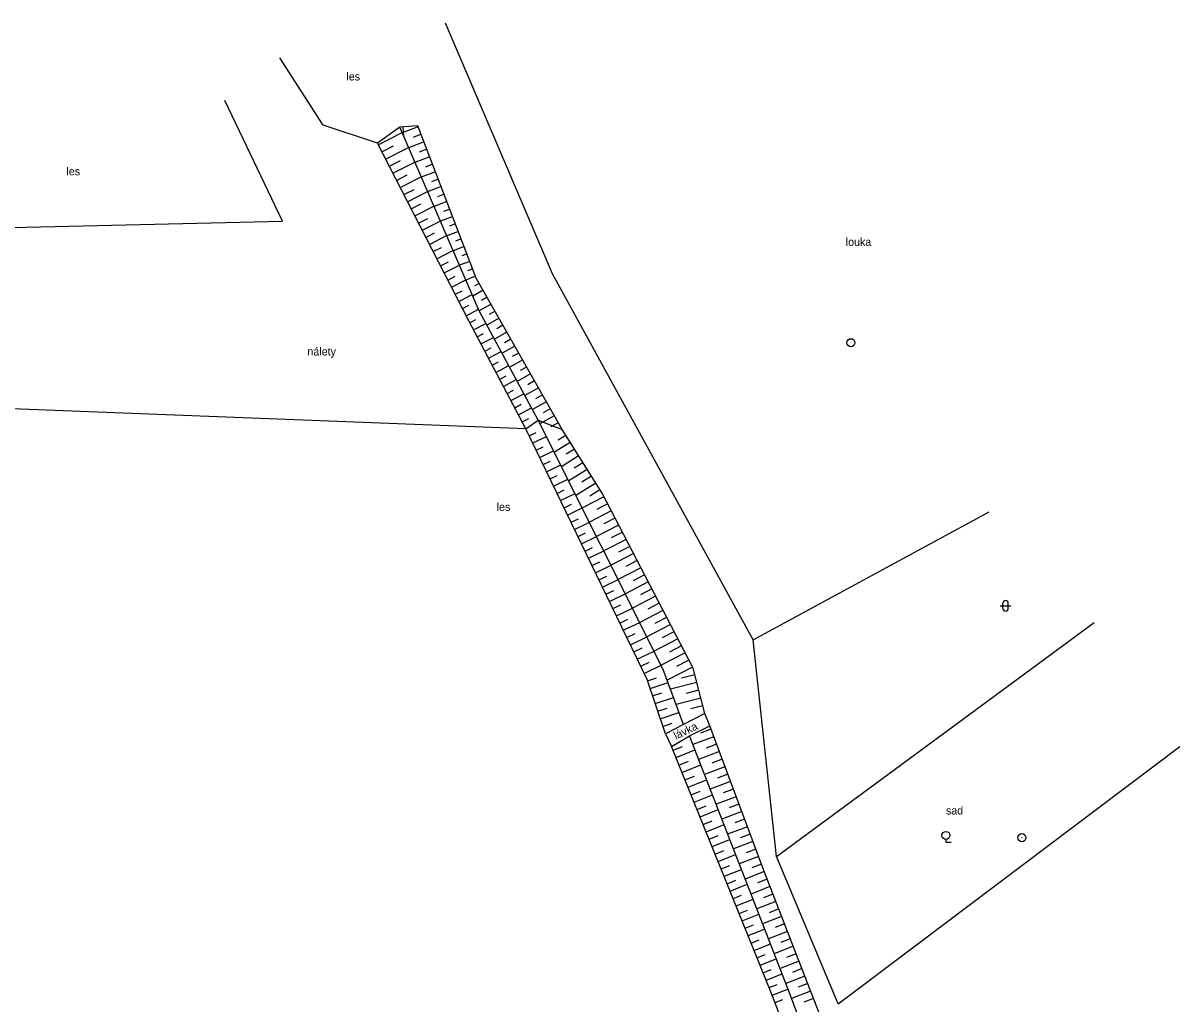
# Model space of a CAD drawing. Extents: x -762483 to -761175, y -1154655 to -1152452.
# Drawn here: x -761757.5 to -761649, y -1152873.6 to -1152781.8 of the extents above; entities that cross this region are included whole.
import ezdxf

# ---------------------------------------------------------------- set-up
doc = ezdxf.new("R2010")
doc.units = 0
for name, color, linetype in [('MAP_ZN_BP', 7, 'Continuous'), ('POMOC_POPIS', 7, 'Continuous'), ('VÝŠKOPIS', 7, 'Continuous'), ('ZELEŇ', 7, 'Continuous'), ('ZN_DOPLŇKOVÉ', 7, 'Continuous'), ('ZN_KULTUR', 7, 'Continuous')]:
    doc.layers.add(name, color=color, linetype=linetype)

msp = doc.modelspace()

# ---------------------------------------------------------------- linework, layer by layer
at = {"layer": 'MAP_ZN_BP'}
for centre, radius in [((-761679.87, -1152811.69), 0.375), ((-761679.87, -1152811.69), 0.0005), ((-761663.84, -1152858.07), 0.375), ((-761663.84, -1152858.07), 0.0005)]:
    msp.add_circle(centre, radius, dxfattribs=at)
at = {"layer": 'VÝŠKOPIS'}
for p, q in [((-761720.43, -1152791.46), (-761721.93, -1152792.04)), ((-761721.87, -1152791.48), (-761721.81, -1152792.34)), ((-761724.18, -1152793.16), (-761721.95, -1152792.01)), ((-761720.16, -1152792.16), (-761720.9, -1152792.45)), ((-761723.84, -1152793.82), (-761722.75, -1152793.26)), ((-761723.5, -1152794.49), (-761721.35, -1152793.39)), ((-761719.89, -1152792.86), (-761721.34, -1152793.42)), ((-761719.62, -1152793.57), (-761720.33, -1152793.84)), ((-761723.16, -1152795.16), (-761722.11, -1152794.62)), ((-761722.81, -1152795.82), (-761720.76, -1152794.77)), ((-761719.35, -1152794.27), (-761720.74, -1152794.8)), ((-761718.81, -1152795.67), (-761720.15, -1152796.18)), ((-761719.08, -1152794.97), (-761719.76, -1152795.23)), ((-761722.47, -1152796.49), (-761721.46, -1152795.97)), ((-761722.13, -1152797.16), (-761720.16, -1152796.15)), ((-761718.55, -1152796.37), (-761719.2, -1152796.62)), ((-761721.78, -1152797.82), (-761720.82, -1152797.33)), ((-761721.44, -1152798.49), (-761719.56, -1152797.53)), ((-761718.28, -1152797.07), (-761719.55, -1152797.55)), ((-761718.01, -1152797.77), (-761718.63, -1152798.01)), ((-761721.1, -1152799.16), (-761720.18, -1152798.69)), ((-761720.75, -1152799.82), (-761718.97, -1152798.91)), ((-761717.74, -1152798.47), (-761718.95, -1152798.93)), ((-761717.47, -1152799.17), (-761718.06, -1152799.39)), ((-761720.41, -1152800.49), (-761719.54, -1152800.04)), ((-761717.2, -1152799.87), (-761718.36, -1152800.31)), ((-761720.07, -1152801.16), (-761718.37, -1152800.29)), ((-761716.66, -1152801.27), (-761717.76, -1152801.69)), ((-761716.93, -1152800.57), (-761717.5, -1152800.78)), ((-761719.72, -1152801.83), (-761718.9, -1152801.4)), ((-761719.38, -1152802.49), (-761717.77, -1152801.66)), ((-761716.4, -1152801.97), (-761716.93, -1152802.17)), ((-761719.04, -1152803.16), (-761718.25, -1152802.76)), ((-761718.69, -1152803.83), (-761717.18, -1152803.04)), ((-761716.13, -1152802.67), (-761717.17, -1152803.07)), ((-761715.86, -1152803.37), (-761716.36, -1152803.56)), ((-761718.35, -1152804.49), (-761717.61, -1152804.11)), ((-761718.01, -1152805.16), (-761716.58, -1152804.42)), ((-761715.59, -1152804.07), (-761716.57, -1152804.44)), ((-761717.66, -1152805.83), (-761716.97, -1152805.47)), ((-761715.05, -1152805.47), (-761715.97, -1152805.82)), ((-761715.32, -1152804.77), (-761715.8, -1152804.95)), ((-761717.32, -1152806.49), (-761715.98, -1152805.8)), ((-761714.71, -1152806.13), (-761715.16, -1152806.39)), ((-761716.98, -1152807.16), (-761716.33, -1152806.83)), ((-761716.63, -1152807.83), (-761715.38, -1152807.18)), ((-761714.34, -1152806.78), (-761715.32, -1152807.34)), ((-761713.97, -1152807.44), (-761714.49, -1152807.73)), ((-761716.29, -1152808.49), (-761715.69, -1152808.18)), ((-761715.95, -1152809.16), (-761714.79, -1152808.56)), ((-761713.6, -1152808.09), (-761714.72, -1152808.72)), ((-761713.23, -1152808.74), (-761713.79, -1152809.06)), ((-761715.6, -1152809.83), (-761715.03, -1152809.52)), ((-761715.25, -1152810.49), (-761714.09, -1152809.88)), ((-761712.86, -1152809.4), (-761714, -1152810.04)), ((-761714.9, -1152811.15), (-761714.32, -1152810.84)), ((-761712.12, -1152810.7), (-761713.29, -1152811.36)), ((-761712.49, -1152810.05), (-761713.07, -1152810.38)), ((-761714.55, -1152811.81), (-761713.38, -1152811.2)), ((-761714.2, -1152812.48), (-761713.61, -1152812.17)), ((-761711.38, -1152812.01), (-761712.58, -1152812.68)), ((-761711.75, -1152811.35), (-761712.34, -1152811.69)), ((-761713.85, -1152813.14), (-761712.67, -1152812.52)), ((-761711.01, -1152812.66), (-761711.62, -1152813)), ((-761713.5, -1152813.8), (-761712.9, -1152813.49)), ((-761713.15, -1152814.47), (-761711.95, -1152813.84)), ((-761710.64, -1152813.31), (-761711.86, -1152814)), ((-761710.27, -1152813.97), (-761710.89, -1152814.31)), ((-761712.8, -1152815.13), (-761712.2, -1152814.81)), ((-761712.44, -1152815.79), (-761711.24, -1152815.15)), ((-761709.9, -1152814.62), (-761711.15, -1152815.32)), ((-761709.54, -1152815.27), (-761710.16, -1152815.63)), ((-761712.09, -1152816.46), (-761711.49, -1152816.13)), ((-761711.74, -1152817.12), (-761710.53, -1152816.47)), ((-761709.17, -1152815.92), (-761710.43, -1152816.64)), ((-761711.39, -1152817.78), (-761710.78, -1152817.46)), ((-761708.43, -1152817.23), (-761709.72, -1152817.96)), ((-761708.8, -1152816.58), (-761709.44, -1152816.94)), ((-761711.04, -1152818.44), (-761709.81, -1152817.79)), ((-761707.69, -1152818.53), (-761709.02, -1152819.29)), ((-761708.06, -1152817.88), (-761708.71, -1152818.25)), ((-761710.69, -1152819.11), (-761710.07, -1152818.78)), ((-761707.32, -1152819.19), (-761708, -1152819.57)), ((-761710.03, -1152820.41), (-761709.39, -1152820.1)), ((-761709.7, -1152821.09), (-761708.42, -1152820.47)), ((-761706.6, -1152820.4), (-761707.31, -1152820.84)), ((-761709.38, -1152821.76), (-761708.73, -1152821.45)), ((-761709.05, -1152822.44), (-761707.75, -1152821.81)), ((-761706.2, -1152821.03), (-761707.67, -1152821.96)), ((-761705.8, -1152821.67), (-761706.57, -1152822.15)), ((-761708.72, -1152823.11), (-761708.07, -1152822.8)), ((-761705.4, -1152822.3), (-761707, -1152823.31)), ((-761705, -1152822.94), (-761705.83, -1152823.46)), ((-761708.4, -1152823.79), (-761707.08, -1152823.15)), ((-761704.6, -1152823.57), (-761706.32, -1152824.65)), ((-761708.07, -1152824.46), (-761707.4, -1152824.14)), ((-761707.74, -1152825.14), (-761706.4, -1152824.49)), ((-761703.8, -1152824.84), (-761705.65, -1152826)), ((-761704.2, -1152824.21), (-761705.09, -1152824.77)), ((-761707.42, -1152825.81), (-761706.74, -1152825.49)), ((-761707.09, -1152826.49), (-761705.73, -1152825.83)), ((-761703.03, -1152826.12), (-761705.05, -1152827.18)), ((-761703.4, -1152825.48), (-761704.36, -1152826.07)), ((-761706.76, -1152827.16), (-761706.08, -1152826.83)), ((-761706.43, -1152827.84), (-761705.06, -1152827.17)), ((-761702.69, -1152826.79), (-761703.7, -1152827.32)), ((-761706.11, -1152828.51), (-761705.41, -1152828.18)), ((-761702.34, -1152827.46), (-761704.38, -1152828.52)), ((-761701.99, -1152828.12), (-761703.02, -1152828.65)), ((-761705.78, -1152829.19), (-761704.38, -1152828.51)), ((-761705.45, -1152829.86), (-761704.75, -1152829.52)), ((-761701.65, -1152828.79), (-761703.71, -1152829.86)), ((-761701.3, -1152829.45), (-761702.34, -1152829.99)), ((-761705.13, -1152830.54), (-761703.71, -1152829.85)), ((-761700.95, -1152830.12), (-761703.03, -1152831.2)), ((-761704.8, -1152831.21), (-761704.09, -1152830.87)), ((-761704.47, -1152831.89), (-761703.04, -1152831.19)), ((-761700.26, -1152831.45), (-761702.36, -1152832.54)), ((-761700.61, -1152830.78), (-761701.65, -1152831.33)), ((-761704.15, -1152832.56), (-761703.42, -1152832.21)), ((-761703.82, -1152833.24), (-761702.36, -1152832.53)), ((-761699.57, -1152832.78), (-761701.69, -1152833.88)), ((-761699.92, -1152832.11), (-761700.97, -1152832.66)), ((-761703.49, -1152833.91), (-761702.76, -1152833.56)), ((-761703.17, -1152834.59), (-761701.69, -1152833.87)), ((-761699.22, -1152833.44), (-761700.29, -1152834)), ((-761702.84, -1152835.26), (-761702.1, -1152834.9)), ((-761698.88, -1152834.11), (-761701.01, -1152835.22)), ((-761698.53, -1152834.77), (-761699.61, -1152835.33)), ((-761702.51, -1152835.94), (-761701.02, -1152835.21)), ((-761698.19, -1152835.44), (-761700.34, -1152836.56)), ((-761702.19, -1152836.61), (-761701.43, -1152836.25)), ((-761701.86, -1152837.29), (-761700.34, -1152836.56)), ((-761697.49, -1152836.77), (-761699.67, -1152837.9)), ((-761697.84, -1152836.11), (-761698.92, -1152836.67)), ((-761701.53, -1152837.96), (-761700.77, -1152837.59)), ((-761701.21, -1152838.64), (-761699.67, -1152837.9)), ((-761696.8, -1152838.1), (-761699, -1152839.24)), ((-761697.15, -1152837.44), (-761698.24, -1152838)), ((-761700.88, -1152839.31), (-761700.11, -1152838.94)), ((-761700.55, -1152839.99), (-761699, -1152839.24)), ((-761696.46, -1152838.77), (-761697.56, -1152839.34)), ((-761700.23, -1152840.66), (-761699.44, -1152840.29)), ((-761696.11, -1152839.43), (-761698.32, -1152840.58)), ((-761695.76, -1152840.1), (-761696.87, -1152840.68)), ((-761699.9, -1152841.34), (-761698.32, -1152840.58)), ((-761695.42, -1152840.76), (-761697.65, -1152841.92)), ((-761695.07, -1152841.43), (-761696.21, -1152842.02)), ((-761699.57, -1152842.01), (-761698.78, -1152841.63)), ((-761699.25, -1152842.69), (-761697.65, -1152841.92)), ((-761694.73, -1152842.09), (-761697.09, -1152843.32)), ((-761698.93, -1152843.37), (-761698.1, -1152843.09)), ((-761698.7, -1152844.08), (-761697.01, -1152843.52)), ((-761694.32, -1152843.54), (-761696.78, -1152844.17)), ((-761694.51, -1152842.81), (-761695.77, -1152843.14)), ((-761698.46, -1152844.79), (-761697.61, -1152844.51)), ((-761694.14, -1152844.26), (-761695.33, -1152844.57)), ((-761698.22, -1152845.5), (-761696.5, -1152844.93)), ((-761693.95, -1152844.99), (-761696.26, -1152845.59)), ((-761693.76, -1152845.71), (-761694.88, -1152846.01)), ((-761697.98, -1152846.22), (-761697.11, -1152845.93)), ((-761697.75, -1152846.93), (-761695.99, -1152846.34)), ((-761697.51, -1152847.64), (-761696.62, -1152847.34)), ((-761692.99, -1152847.9), (-761693.97, -1152848.27)), ((-761692.72, -1152848.61), (-761694.69, -1152849.34)), ((-761696.55, -1152849.88), (-761695.66, -1152849.52)), ((-761696.27, -1152850.57), (-761694.49, -1152849.85)), ((-761692.2, -1152850.01), (-761694.15, -1152850.74)), ((-761692.46, -1152849.31), (-761693.44, -1152849.67)), ((-761695.99, -1152851.27), (-761695.1, -1152850.91)), ((-761691.94, -1152850.71), (-761692.91, -1152851.08)), ((-761695.71, -1152851.96), (-761693.95, -1152851.25)), ((-761695.43, -1152852.66), (-761694.55, -1152852.3)), ((-761691.68, -1152851.42), (-761693.6, -1152852.14)), ((-761691.41, -1152852.12), (-761692.37, -1152852.48)), ((-761695.14, -1152853.35), (-761693.4, -1152852.65)), ((-761691.15, -1152852.82), (-761693.06, -1152853.53)), ((-761694.86, -1152854.05), (-761694, -1152853.7)), ((-761694.58, -1152854.74), (-761692.86, -1152854.05)), ((-761690.63, -1152854.23), (-761692.51, -1152854.93)), ((-761690.89, -1152853.53), (-761691.84, -1152853.88)), ((-761694.3, -1152855.44), (-761693.44, -1152855.09)), ((-761694.02, -1152856.13), (-761692.32, -1152855.44)), ((-761690.37, -1152854.93), (-761691.3, -1152855.28)), ((-761693.73, -1152856.83), (-761692.89, -1152856.49)), ((-761690.1, -1152855.63), (-761691.97, -1152856.33)), ((-761689.84, -1152856.34), (-761690.77, -1152856.68)), ((-761693.45, -1152857.52), (-761691.77, -1152856.84)), ((-761689.58, -1152857.04), (-761691.43, -1152857.73)), ((-761689.32, -1152857.74), (-761690.24, -1152858.08)), ((-761693.17, -1152858.22), (-761692.33, -1152857.88)), ((-761692.89, -1152858.91), (-761691.23, -1152858.24)), ((-761689.06, -1152858.44), (-761690.88, -1152859.13)), ((-761692.61, -1152859.61), (-761691.78, -1152859.27)), ((-761692.32, -1152860.3), (-761690.68, -1152859.64)), ((-761688.53, -1152859.85), (-761690.34, -1152860.52)), ((-761688.79, -1152859.15), (-761689.7, -1152859.49)), ((-761692.04, -1152861), (-761691.23, -1152860.67)), ((-761688.27, -1152860.55), (-761689.17, -1152860.89)), ((-761691.76, -1152861.69), (-761690.14, -1152861.04)), ((-761691.48, -1152862.39), (-761690.67, -1152862.06)), ((-761688.01, -1152861.25), (-761689.78, -1152861.95)), ((-761687.73, -1152861.95), (-761688.62, -1152862.3)), ((-761691.2, -1152863.08), (-761689.59, -1152862.43)), ((-761687.46, -1152862.65), (-761689.24, -1152863.35)), ((-761690.91, -1152863.78), (-761690.12, -1152863.46)), ((-761690.63, -1152864.47), (-761689.05, -1152863.83)), ((-761686.92, -1152864.05), (-761688.7, -1152864.74)), ((-761687.19, -1152863.35), (-761688.08, -1152863.7)), ((-761690.35, -1152865.17), (-761689.56, -1152864.85)), ((-761690.07, -1152865.86), (-761688.51, -1152865.23)), ((-761686.64, -1152864.75), (-761687.53, -1152865.1)), ((-761689.79, -1152866.56), (-761689.01, -1152866.24)), ((-761686.37, -1152865.45), (-761688.15, -1152866.14)), ((-761686.1, -1152866.15), (-761686.99, -1152866.49)), ((-761689.5, -1152867.25), (-761687.96, -1152866.63)), ((-761685.83, -1152866.85), (-761687.61, -1152867.54)), ((-761689.22, -1152867.95), (-761688.46, -1152867.64)), ((-761688.94, -1152868.64), (-761687.42, -1152868.03)), ((-761685.28, -1152868.24), (-761687.06, -1152868.94)), ((-761685.56, -1152867.54), (-761686.45, -1152867.89)), ((-761688.66, -1152869.34), (-761687.9, -1152869.03)), ((-761688.38, -1152870.03), (-761686.87, -1152869.42)), ((-761684.74, -1152869.64), (-761686.52, -1152870.33)), ((-761685.01, -1152868.94), (-761685.9, -1152869.29)), ((-761688.09, -1152870.73), (-761687.35, -1152870.43)), ((-761684.47, -1152870.34), (-761685.36, -1152870.69)), ((-761687.81, -1152871.42), (-761686.33, -1152870.82)), ((-761687.53, -1152872.12), (-761686.79, -1152871.82)), ((-761684.2, -1152871.04), (-761685.98, -1152871.73)), ((-761683.92, -1152871.74), (-761684.81, -1152872.09)), ((-761687.25, -1152872.82), (-761685.78, -1152872.25)), ((-761683.65, -1152872.44), (-761685.44, -1152873.13)), ((-761686.98, -1152873.52), (-761686.25, -1152873.23)), ((-761683.38, -1152873.14), (-761684.28, -1152873.49))]:
    msp.add_line(p, q, dxfattribs=at)
for points in [[(-761695.57, -1152847.48), (-761697.46, -1152842.3), (-761709.18, -1152818.96), (-761714.72, -1152808.72), (-761722.17, -1152791.5)], [(-761710.34, -1152819.77), (-761715.7, -1152809.64), (-761724.26, -1152793.01)], [(-761693.57, -1152846.44), (-761694.67, -1152842.2), (-761703.2, -1152825.8), (-761706.95, -1152819.84)], [(-761677.12, -1152889.21), (-761688.05, -1152861.14), (-761693.1, -1152847.6)], [(-761669.82, -1152918.75), (-761675.11, -1152902.44), (-761677.96, -1152893.06), (-761685.79, -1152872.21), (-761695.01, -1152848.52)]]:
    msp.add_lwpolyline(points, dxfattribs=at)
at = {"layer": 'ZELEŇ'}
for p, q in [((-761689.03, -1152839.53), (-761666.9, -1152827.55)), ((-761686.84, -1152859.84), (-761657.07, -1152837.92)), ((-761686.84, -1152859.84), (-761689.03, -1152839.53)), ((-761681.06, -1152873.63), (-761649.04, -1152849.52)), ((-761681.06, -1152873.63), (-761686.84, -1152859.84))]:
    msp.add_line(p, q, dxfattribs=at)
for points in [[(-761689.03, -1152839.53), (-761707.85, -1152805.23), (-761717.87, -1152781.75)], [(-761724.26, -1152793.01), (-761729.34, -1152791.3), (-761733.4, -1152785.01)], [(-761811.31, -1152796.07), (-761794.23, -1152801.04), (-761778.98, -1152801.39), (-761770.57, -1152801.17), (-761733.15, -1152800.31), (-761738.57, -1152789)], [(-761706.95, -1152819.84), (-761714.99, -1152805.63), (-761720.46, -1152791.38), (-761722.17, -1152791.5), (-761724.26, -1152793.01)], [(-761710.34, -1152819.77), (-761760.97, -1152817.79), (-761782.81, -1152826.59)], [(-761710.34, -1152819.77), (-761709.18, -1152818.96), (-761706.95, -1152819.84)], [(-761697.27, -1152848.35), (-761698.97, -1152843.26), (-761710.34, -1152819.77)], [(-761676.14, -1152903.87), (-761679.31, -1152893.53), (-761687.37, -1152872.51), (-761696.7, -1152849.52)]]:
    msp.add_lwpolyline(points, dxfattribs=at)
at = {"layer": 'ZN_DOPLŇKOVÉ'}
msp.add_lwpolyline([(-761697.27, -1152848.35), (-761696.7, -1152849.52), (-761695.01, -1152848.52), (-761693.1, -1152847.6), (-761693.57, -1152846.44), (-761695.57, -1152847.48), (-761697.27, -1152848.35)], dxfattribs=at)
at = {"layer": 'ZN_KULTUR'}
for p, q in [((-761665.87, -1152836.35), (-761664.87, -1152836.35)), ((-761665.62, -1152836.6), (-761665.62, -1152836.1)), ((-761665.12, -1152836.6), (-761665.12, -1152836.1))]:
    msp.add_line(p, q, dxfattribs=at)
msp.add_lwpolyline([(-761670.97, -1152858.24), (-761670.97, -1152858.49), (-761670.47, -1152858.49)], dxfattribs=at)
msp.add_circle((-761670.97, -1152857.86), 0.375, dxfattribs=at)
for centre, start, end in [((-761665.37, -1152836.1), 0, 180), ((-761665.37, -1152836.6), 180, 360)]:
    msp.add_arc(centre, 0.25, start, end, dxfattribs=at)

# ---------------------------------------------------------------- texts
at = {"layer": 'POMOC_POPIS'}
msp.add_text('lávka', height=0.75, rotation=25.92, dxfattribs=at).set_placement((-761696.27, -1152848.9))
at = {"layer": 'ZELEŇ'}
for s, p in [('les', (-761727.17, -1152787.12)), ('les', (-761753.41, -1152796.01)), ('louka', (-761680.36, -1152802.62)), ('nálety', (-761730.82, -1152812.89)), ('les', (-761713.08, -1152827.45)), ('sad', (-761670.97, -1152855.9))]:
    msp.add_text(s, height=0.75, dxfattribs=at).set_placement(p)

doc.saveas('drawing.dxf')
